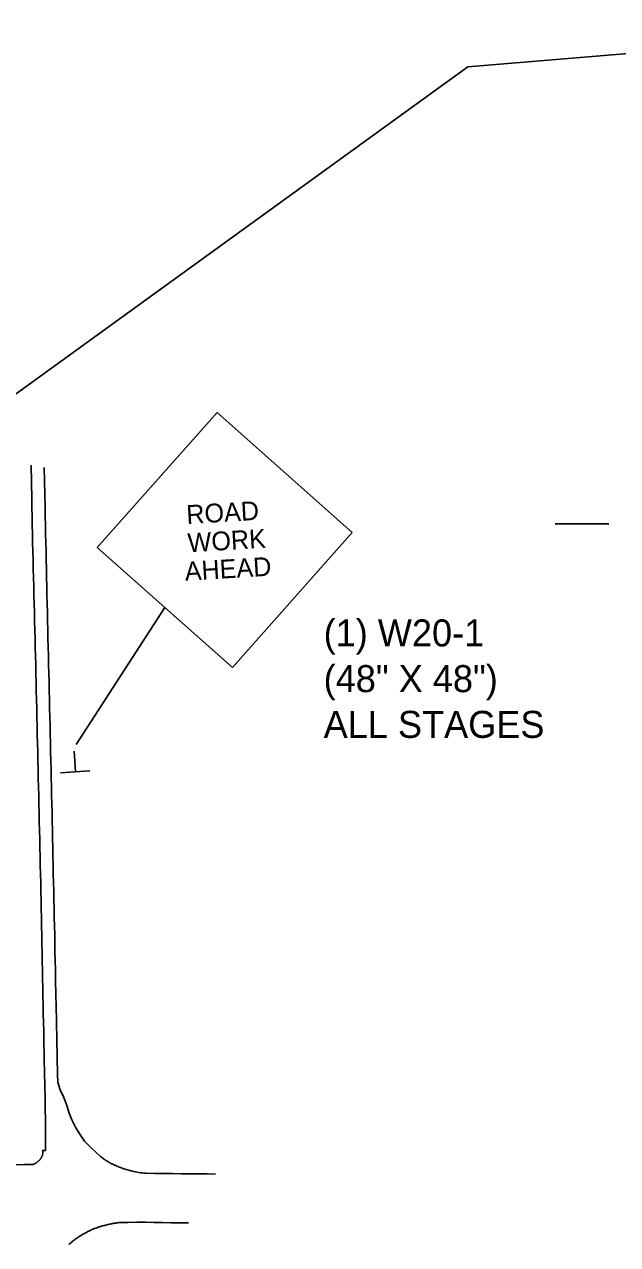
# Model space of a CAD drawing. Extents: x 1017892 to 1236694, y 658811 to 792468.
# Drawn here: x 1023001 to 1023342, y 659687 to 660387 of the extents above; entities that cross this region are included whole.
import ezdxf

# ---------------------------------------------------------------- set-up
doc = ezdxf.new("R2010")
doc.units = 0
for name, color, linetype in [('Level 3', 7, 'Continuous'), ('Level 8', 7, 'Continuous'), ('R_Border', 7, 'Continuous'), ('R_Draft', 7, 'Continuous'), ('R_Proposed Road Annot', 7, 'Continuous'), ('S_EDGE_PAVEMENT', 7, 'Continuous')]:
    doc.layers.add(name, color=color, linetype=linetype)

msp = doc.modelspace()

# ---------------------------------------------------------------- linework, layer by layer
at = {"layer": 'Level 3'}
for p, q in [((1023030.44, 659958.66), (1023029.76, 659970.16)), ((1023038.84, 659958.91), (1023021.99, 659957.91))]:
    msp.add_line(p, q, dxfattribs=at)
at = {"layer": 'Level 8'}
for p, q in [((1023111.86, 660164.47), (1023043.04, 660086.96)), ((1023189.38, 660095.64), (1023111.86, 660164.47)), ((1023189.38, 660095.64), (1023120.55, 660018.19)), ((1023120.55, 660018.19), (1023043.04, 660086.96))]:
    msp.add_line(p, q, dxfattribs=at)
at = {"layer": 'R_Border'}
msp.add_lwpolyline([(1023548.14, 660387), (1023255.62, 660362.67), (1022921.74, 660121.31)], dxfattribs=at)
at = {"layer": 'R_Draft'}
msp.add_line((1023305.74, 660100.56), (1023336.59, 660100.56), dxfattribs=at)
at = {"layer": 'R_Proposed Road Annot'}
msp.add_line((1023030.95, 659974.1), (1023081.79, 660052.57), dxfattribs=at)
at = {"layer": 'S_EDGE_PAVEMENT'}
for points in [[(1023006.28, 659733.32), (1023006.49, 659733.41), (1023006.71, 659733.5), (1023006.93, 659733.6), (1023007.14, 659733.71), (1023007.36, 659733.82), (1023007.57, 659733.94), (1023007.78, 659734.06), (1023007.98, 659734.19), (1023008.18, 659734.32), (1023008.38, 659734.46), (1023008.58, 659734.61), (1023008.77, 659734.76), (1023008.96, 659734.92), (1023009.15, 659735.08), (1023009.33, 659735.25), (1023009.51, 659735.42), (1023009.68, 659735.59), (1023009.85, 659735.77), (1023010.01, 659735.96), (1023010.17, 659736.14), (1023010.32, 659736.34), (1023010.47, 659736.53), (1023010.61, 659736.73), (1023010.74, 659736.93), (1023010.87, 659737.14), (1023011, 659737.35), (1023011.12, 659737.56), (1023011.23, 659737.77), (1023011.34, 659737.98), (1023011.44, 659738.2), (1023011.53, 659738.42), (1023011.62, 659738.63), (1023011.71, 659739.98), (1023011.69, 659740.47), (1023011.66, 659741.25), (1023013.22, 659741.26), (1023013.32, 659744.9), (1023013.3, 659749.68), (1023013.3, 659754.68), (1023013.27, 659759.68), (1023013.18, 659764.61), (1023013.03, 659769.58), (1023012.86, 659779.62), (1023012.76, 659784.72), (1023012.6, 659794.73), (1023012.42, 659804.74), (1023012.32, 659809.76), (1023012.15, 659814.75), (1023012.03, 659819.77), (1023011.92, 659824.82), (1023011.85, 659829.83), (1023011.73, 659834.76), (1023011.64, 659839.68), (1023011.52, 659844.67), (1023011.42, 659849.66), (1023011.34, 659854.66), (1023011.27, 659859.6), (1023011.13, 659864.59), (1023011.08, 659869.83), (1023010.97, 659874.83), (1023010.86, 659879.83), (1023010.75, 659884.82), (1023010.65, 659889.82), (1023010.54, 659894.82), (1023010.43, 659899.82), (1023010.32, 659904.82), (1023010.21, 659909.82), (1023010.1, 659914.82), (1023009.98, 659919.82), (1023009.87, 659924.82), (1023009.75, 659929.81), (1023009.64, 659934.81), (1023009.52, 659939.81), (1023009.41, 659944.81), (1023009.3, 659949.81), (1023009.18, 659954.81), (1023009.07, 659959.81), (1023008.96, 659964.81), (1023008.84, 659969.81), (1023008.73, 659974.8), (1023008.62, 659979.8), (1023008.5, 659984.8), (1023008.38, 659989.8), (1023008.26, 659994.8), (1023008.15, 659999.8), (1023008.03, 660004.84), (1023007.91, 660009.84), (1023007.79, 660014.84), (1023007.67, 660019.84), (1023007.55, 660024.84), (1023007.43, 660029.84), (1023007.31, 660034.84), (1023007.19, 660039.84), (1023007.07, 660044.84), (1023006.95, 660049.83), (1023006.83, 660054.83), (1023006.7, 660059.83), (1023006.57, 660064.83), (1023006.44, 660069.83), (1023006.31, 660074.83), (1023006.19, 660079.83), (1023006.06, 660084.83), (1023005.94, 660089.83), (1023005.82, 660094.83), (1023005.72, 660099.83), (1023005.63, 660104.83), (1023005.53, 660109.83), (1023005.44, 660114.83), (1023005.06, 660134.31)], [(1023012.59, 660132.95), (1023013.06, 660109.9), (1023013.16, 660104.9), (1023013.27, 660099.9), (1023013.38, 660094.9), (1023013.49, 660089.9), (1023013.6, 660084.9), (1023013.71, 660079.9), (1023013.82, 660074.9), (1023013.93, 660069.9), (1023014.04, 660064.9), (1023014.15, 660059.91), (1023014.27, 660054.91), (1023014.38, 660049.91), (1023014.5, 660044.91), (1023014.62, 660039.91), (1023014.74, 660034.91), (1023014.86, 660029.91), (1023014.98, 660024.91), (1023015.09, 660019.91), (1023015.21, 660014.91), (1023015.33, 660009.91), (1023015.45, 660004.91), (1023015.58, 659999.96), (1023015.7, 659994.97), (1023015.82, 659989.97), (1023015.95, 659984.97), (1023016.06, 659979.97), (1023016.16, 659974.97), (1023016.27, 659969.97), (1023016.38, 659964.97), (1023016.49, 659959.97), (1023016.6, 659954.98), (1023016.72, 659949.98), (1023016.83, 659944.98), (1023016.94, 659939.98), (1023017.06, 659934.98), (1023017.17, 659929.98), (1023017.28, 659924.98), (1023017.39, 659919.98), (1023017.49, 659914.98), (1023017.59, 659909.99), (1023017.7, 659904.99), (1023017.8, 659899.99), (1023017.9, 659894.99), (1023018.01, 659889.99), (1023018.12, 659884.99), (1023018.23, 659879.99), (1023018.34, 659874.99), (1023018.45, 659869.99), (1023018.6, 659865.03), (1023018.69, 659860.02), (1023018.75, 659854.97), (1023018.87, 659849.97), (1023018.98, 659844.96), (1023019.05, 659839.95), (1023019.31, 659829.76), (1023019.36, 659824.76), (1023019.64, 659814.82), (1023019.88, 659804.84), (1023020.08, 659794.85), (1023020.27, 659784.86), (1023020.35, 659780.41), (1023021.8, 659776.09), (1023023.8, 659771.67), (1023025.57, 659767.14), (1023026.89, 659762.63), (1023028.36, 659758.91), (1023030.5, 659754.57), (1023033.03, 659750.56), (1023035.6, 659746.53), (1023039.12, 659743.11), (1023042.14, 659740.25), (1023044.85, 659737.91), (1023045.27, 659737.55), (1023045.71, 659737.2), (1023046.15, 659736.87), (1023046.59, 659736.53), (1023047.04, 659736.21), (1023047.5, 659735.89), (1023047.96, 659735.58), (1023048.43, 659735.28), (1023048.9, 659734.98), (1023049.38, 659734.7), (1023049.86, 659734.42), (1023050.34, 659734.15), (1023050.83, 659733.89), (1023051.33, 659733.64), (1023051.83, 659733.39), (1023052.33, 659733.16), (1023052.98, 659732.86), (1023053.63, 659732.57), (1023054.29, 659732.29), (1023054.95, 659732.02), (1023055.62, 659731.75), (1023056.29, 659731.49), (1023056.96, 659731.25), (1023057.63, 659731), (1023058.31, 659730.77), (1023058.99, 659730.55), (1023059.67, 659730.33), (1023060.36, 659730.13), (1023061.05, 659729.93), (1023061.74, 659729.74), (1023062.43, 659729.56), (1023063.12, 659729.38), (1023064.08, 659729.19), (1023065.03, 659729), (1023065.99, 659728.84), (1023066.95, 659728.68), (1023067.92, 659728.54), (1023068.88, 659728.41), (1023069.85, 659728.3), (1023070.82, 659728.2)], [(1022904.19, 659730.24), (1022912.1, 659730.42), (1022917.11, 659730.56), (1022922.12, 659730.71), (1022927.12, 659730.85), (1022932.13, 659730.99), (1022937.13, 659731.13), (1022942.14, 659731.27), (1022947.15, 659731.42), (1022952.15, 659731.57), (1022957.16, 659731.72), (1022962.17, 659731.88), (1022967.17, 659732.02), (1022972.18, 659732.16), (1022977.19, 659732.33), (1022982.19, 659732.52), (1022987.2, 659732.7), (1022992.21, 659732.84), (1022995.86, 659732.95), (1023001.1, 659733.15), (1023006.28, 659733.32)], [(1023070.82, 659728.2), (1023076.14, 659728.15), (1023081.14, 659728.06), (1023086.14, 659728.04), (1023091.14, 659727.97), (1023096.1, 659727.92), (1023101.1, 659727.83), (1023106.1, 659727.8), (1023110.88, 659727.7)], [(1023035.16, 659693.4), (1023035.17, 659693.4), (1023035.77, 659693.76), (1023036.38, 659694.11), (1023037, 659694.45), (1023037.62, 659694.78), (1023038.25, 659695.1), (1023038.88, 659695.41), (1023039.52, 659695.7), (1023040.17, 659695.99), (1023040.82, 659696.26), (1023041.48, 659696.52), (1023042.14, 659696.77), (1023042.8, 659697.01), (1023043.47, 659697.23), (1023044.14, 659697.45), (1023044.82, 659697.65), (1023045.49, 659697.84), (1023046.11, 659698.01), (1023046.73, 659698.18), (1023047.35, 659698.35), (1023047.97, 659698.51), (1023048.59, 659698.66), (1023049.22, 659698.81), (1023049.84, 659698.95), (1023050.47, 659699.08), (1023051.1, 659699.21), (1023051.73, 659699.33), (1023052.36, 659699.44), (1023052.99, 659699.55), (1023053.63, 659699.65), (1023054.26, 659699.75), (1023054.89, 659699.83), (1023055.53, 659699.92)], [(1023095.42, 659699.77), (1023090.39, 659699.86), (1023085.38, 659699.88), (1023080.38, 659699.95), (1023075.39, 659700.04), (1023070.71, 659700.09), (1023065.71, 659700.13), (1023060.7, 659700.03), (1023055.53, 659699.92)], [(1023026.66, 659687.31), (1023027.15, 659687.74), (1023027.64, 659688.17), (1023028.15, 659688.59), (1023028.65, 659689.01), (1023029.17, 659689.41), (1023029.68, 659689.82), (1023030.21, 659690.21), (1023030.74, 659690.6), (1023031.28, 659690.97), (1023031.82, 659691.34), (1023032.36, 659691.71), (1023032.91, 659692.06), (1023033.47, 659692.41), (1023034.03, 659692.75), (1023034.6, 659693.08), (1023035.16, 659693.4)]]:
    msp.add_lwpolyline(points, dxfattribs=at)

# ---------------------------------------------------------------- texts
at = {"layer": 'Level 8'}
for s, rotation, p in [('ROAD', 3.39652, (1023094.45, 660100.47)), ('WORK', 3.39611, (1023095.2, 660084.28)), ('AHEAD', 3.39664, (1023093.53, 660067.96))]:
    msp.add_text(s, height=10.799, rotation=rotation, dxfattribs=at).set_placement(p)
for s, p in [('(1) W20-1', (1023172.94, 660030.31)), ('(48" X 48")', (1023172.94, 660004.09)), ('ALL STAGES', (1023172.94, 659977.86))]:
    msp.add_text(s, height=15.5, dxfattribs=at).set_placement(p)

doc.saveas('drawing.dxf')
